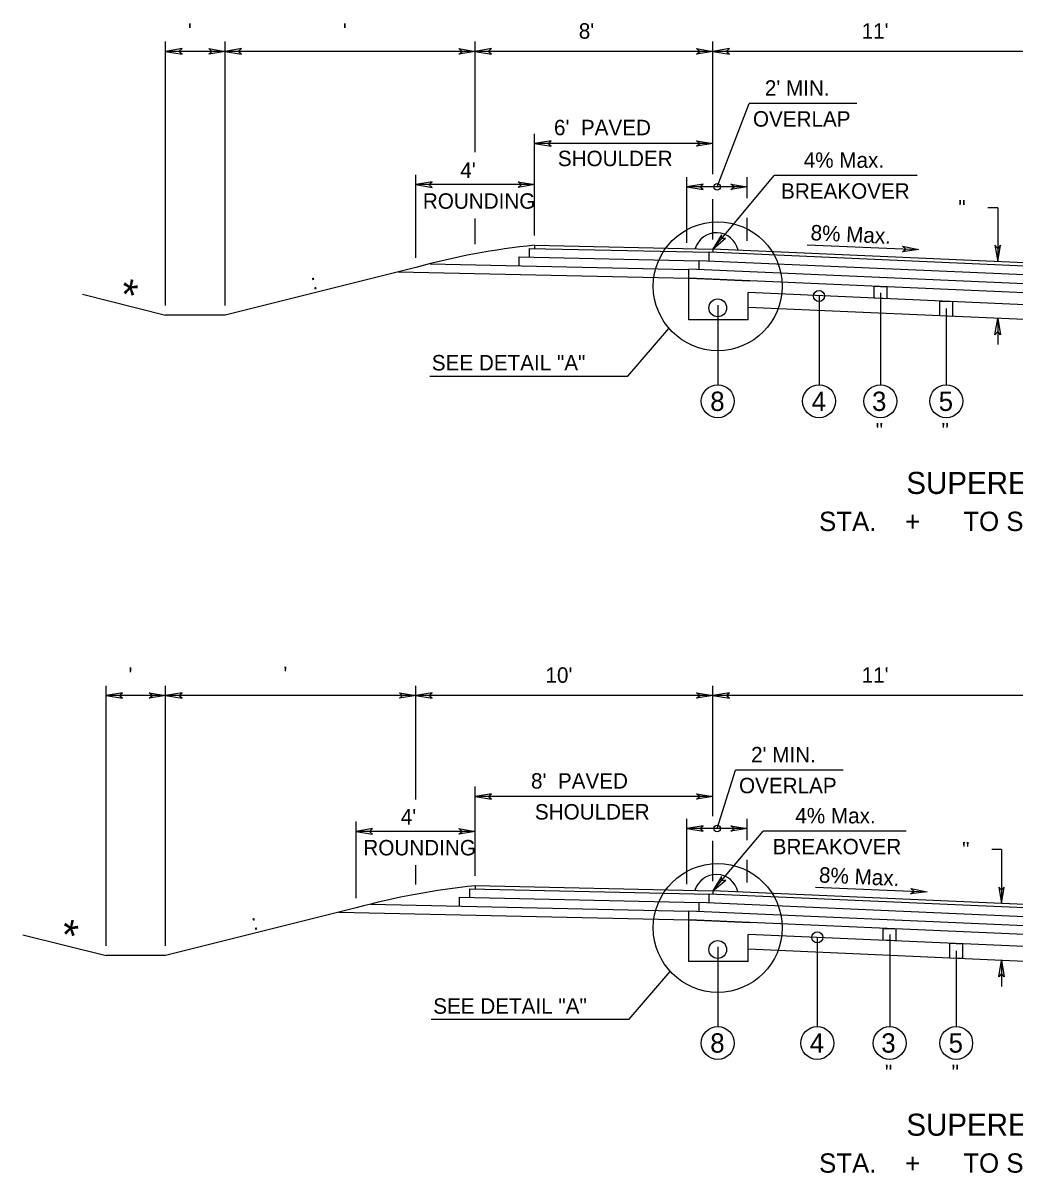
# Model space of a CAD drawing. Extents: x -592 to 1199, y -590 to 416.
# Drawn here: x 724.3 to 814.1, y 44 to 148.2 of the extents above; entities that cross this region are included whole.
import ezdxf

# ---------------------------------------------------------------- set-up
doc = ezdxf.new("R2010")
doc.units = 0
doc.layers.add('1', color=7, linetype='Continuous')
doc.layers.add('Des_ Drain_ Ftrs', color=7, linetype='Continuous')

msp = doc.modelspace()

# ---------------------------------------------------------------- linework, layer by layer
at = {"layer": '1'}
for p, q in [((737.21, 122.56), (737.21, 146.46)), ((742.6, 122.56), (742.6, 146.46)), ((765.26, 136.44), (765.26, 146.46)), ((786.81, 134.44), (786.81, 146.46)), ((742.6, 145.58), (737.21, 145.58)), ((765.26, 145.58), (742.6, 145.58)), ((786.81, 145.58), (765.26, 145.58)), ((816.45, 145.58), (786.81, 145.58)), ((787.18, 133.31), (790.09, 140.86)), ((799.85, 140.86), (790.09, 140.86)), ((770.65, 128.89), (770.65, 138.12)), ((786.81, 137.24), (770.65, 137.24)), ((759.87, 126.88), (759.87, 134.39)), ((770.65, 133.51), (759.87, 133.51)), ((784.44, 128.23), (784.44, 134.19)), ((786.81, 127.66), (792.34, 134.33)), ((789.92, 132.29), (789.92, 134.19)), ((805.31, 134.33), (792.34, 134.33)), ((789.92, 133.31), (784.44, 133.31)), ((786.81, 128.54), (786.81, 132.18)), ((812.61, 131.41), (811.73, 131.41)), ((812.61, 131.41), (812.61, 126.53)), ((765.26, 128.12), (765.26, 130.44)), ((789.92, 128.41), (789.92, 130.51)), ((770.18, 127.72), (786.47, 127.38)), ((770.18, 126.94), (770.18, 127.72)), ((770.65, 128.01), (786.81, 127.66)), ((770.65, 128.01), (770.65, 127.71)), ((816.45, 126.07), (786.47, 127.38)), ((786.47, 126.57), (786.47, 127.38)), ((816.45, 126.37), (786.81, 127.66)), ((786.81, 127.66), (786.81, 127.36)), ((795.35, 128.06), (805.46, 127.62)), ((761.17, 126.34), (784.58, 125.83)), ((769.25, 126.96), (785.52, 126.6)), ((769.25, 126.17), (769.25, 126.96)), ((816.45, 125.26), (785.55, 126.61)), ((785.55, 125.8), (785.55, 126.61)), ((759.87, 126), (742.6, 121.68)), ((758.28, 125.6), (784.62, 125.03)), ((816.45, 124.45), (784.62, 125.84)), ((784.62, 125.03), (784.62, 125.84)), ((784.62, 121.27), (784.62, 125.03)), ((816.45, 123.64), (784.62, 125.03)), ((784.62, 125.03), (786.81, 124.93)), ((786.81, 124.93), (790.11, 124.79)), ((729.67, 123.57), (737.21, 121.68)), ((816.45, 122.56), (790.01, 123.72)), ((790.01, 121.27), (790.01, 123.72)), ((796.42, 123.42), (796.42, 115.36)), ((801.98, 123.71), (801.98, 115.36)), ((787.24, 122.58), (787.24, 122.58)), ((787.24, 122.58), (787.24, 115.36)), ((816.45, 121.21), (790.01, 122.37)), ((807.95, 122.28), (807.95, 115.36)), ((742.6, 121.68), (737.21, 121.68)), ((790.01, 121.27), (784.62, 121.27)), ((812.61, 121.38), (812.61, 119.01)), ((779.08, 116.16), (782.82, 120.48)), ((761.15, 116.16), (779.08, 116.16)), ((731.82, 64.54), (731.82, 88.09)), ((737.21, 64.54), (737.21, 88.09)), ((759.87, 77.81), (759.87, 88.09)), ((786.81, 76.29), (786.81, 88.09)), ((737.21, 87.21), (731.82, 87.21)), ((759.87, 87.21), (737.21, 87.21)), ((786.81, 87.21), (759.87, 87.21)), ((816.45, 87.21), (786.81, 87.21)), ((787.18, 75.17), (788.84, 80.46)), ((798.6, 80.46), (788.84, 80.46)), ((765.26, 70.87), (765.26, 78.96)), ((786.81, 78.08), (765.26, 78.08)), ((754.49, 68.86), (754.49, 75.79)), ((784.44, 70.11), (784.44, 76.05)), ((789.92, 75.17), (784.44, 75.17)), ((789.92, 74.1), (789.92, 76.05)), ((765.26, 74.91), (754.49, 74.91)), ((786.81, 69.52), (791.37, 74.93)), ((786.81, 70.4), (786.81, 74.04)), ((804.3, 74.93), (791.37, 74.93)), ((812.96, 73.25), (812.08, 73.25)), ((812.96, 73.25), (812.96, 68.37)), ((789.92, 70.26), (789.92, 72.32)), ((759.87, 70.09), (759.87, 71.85)), ((765.26, 69.99), (786.81, 69.52)), ((765.26, 69.99), (765.26, 69.69)), ((796.1, 69.86), (806.22, 69.42)), ((763.84, 68.94), (785.55, 68.46)), ((763.84, 68.15), (763.84, 68.94)), ((764.77, 69.7), (786.47, 69.23)), ((764.77, 68.92), (764.77, 69.7)), ((816.45, 67.92), (786.47, 69.23)), ((786.47, 68.42), (786.47, 69.23)), ((816.45, 68.22), (786.81, 69.52)), ((786.81, 69.52), (786.81, 69.22)), ((754.49, 67.98), (737.21, 63.66)), ((755.81, 68.32), (784.62, 67.69)), ((816.45, 67.11), (785.55, 68.46)), ((785.55, 67.65), (785.55, 68.46)), ((752.89, 67.58), (784.62, 66.88)), ((816.45, 66.3), (784.62, 67.69)), ((784.62, 66.88), (784.62, 67.69)), ((784.62, 63.13), (784.62, 66.88)), ((816.45, 65.5), (784.62, 66.88)), ((784.62, 66.88), (786.81, 66.79)), ((786.81, 66.79), (790.11, 66.65)), ((724.28, 65.54), (731.82, 63.66)), ((816.45, 64.42), (790.01, 65.57)), ((790.01, 63.13), (790.01, 65.57)), ((796.26, 65.3), (796.26, 57.22)), ((802.82, 65.55), (802.82, 57.22)), ((737.21, 63.66), (731.82, 63.66)), ((787.24, 64.44), (787.24, 64.44)), ((787.24, 64.44), (787.24, 57.22)), ((816.45, 63.07), (790.01, 64.22)), ((808.85, 64.08), (808.85, 57.22)), ((790.01, 63.13), (784.62, 63.13)), ((812.96, 63.22), (812.96, 60.85)), ((779.2, 57.88), (782.94, 62.2)), ((761.27, 57.88), (779.2, 57.88))]:
    msp.add_line(p, q, dxfattribs=at)
for points in [[(801.41, 124.3), (802.55, 124.25), (802.55, 123.17), (801.41, 123.22)], [(807.37, 122.96), (808.52, 122.91), (808.52, 121.56), (807.37, 121.61)], [(802.24, 66.12), (803.39, 66.07), (803.39, 64.99), (802.24, 65.04)], [(808.28, 64.77), (809.43, 64.72), (809.43, 63.38), (808.28, 63.43)]]:
    msp.add_lwpolyline(points, close=True, dxfattribs=at)
for centre, radius in [((787.18, 133.31), 0.3), ((787.24, 124.3), 5.84), ((787.24, 122.34), 0.808), ((796.42, 123.42), 0.5), ((787.24, 113.88), 1.49), ((796.42, 113.88), 1.49), ((801.98, 113.88), 1.49), ((807.95, 113.88), 1.49), ((787.18, 75.17), 0.3), ((787.24, 66.16), 5.84), ((796.26, 65.3), 0.5), ((787.24, 64.2), 0.808), ((787.24, 55.73), 1.49), ((796.26, 55.73), 1.49), ((802.82, 55.73), 1.49), ((808.85, 55.73), 1.49)]:
    msp.add_circle(centre, radius, dxfattribs=at)
for centre, radius, start, end in [((787.12, 127.15), 2, 12.002, 163.9183), ((777.54, 61.18), 67.19, 95.8897, 105.2483), ((787.1, 69), 2, 12.0711, 163.96), ((772.16, 3.15), 67.19, 95.8911, 105.2497)]:
    msp.add_arc(centre, radius, start, end, dxfattribs=at)
at = {"layer": 'Des_ Drain_ Ftrs'}
for points in [[(737.21, 145.58), (738.7, 145.33), (738.4, 145.58), (738.7, 145.83)], [(742.6, 145.58), (741.11, 145.33), (741.4, 145.58), (741.11, 145.83)], [(742.6, 145.58), (744.08, 145.33), (743.79, 145.58), (744.08, 145.83)], [(765.26, 145.58), (763.77, 145.33), (764.07, 145.58), (763.77, 145.83)], [(765.26, 145.58), (766.75, 145.33), (766.45, 145.58), (766.75, 145.83)], [(786.81, 145.58), (785.33, 145.33), (785.62, 145.58), (785.33, 145.83)], [(786.81, 145.58), (788.3, 145.33), (788.01, 145.58), (788.3, 145.83)], [(770.65, 137.24), (772.14, 136.99), (771.84, 137.24), (772.14, 137.48)], [(786.81, 137.24), (785.33, 136.99), (785.62, 137.24), (785.33, 137.48)], [(759.87, 133.51), (761.36, 133.26), (761.07, 133.51), (761.36, 133.75)], [(770.65, 133.51), (769.16, 133.26), (769.46, 133.51), (769.16, 133.75)], [(784.44, 133.31), (785.93, 133.06), (785.63, 133.31), (785.93, 133.56)], [(789.92, 133.31), (788.44, 133.06), (788.73, 133.31), (788.44, 133.56)], [(786.81, 127.66), (787.95, 128.65), (787.57, 128.58), (787.57, 128.96)], [(805.46, 127.62), (803.97, 127.43), (804.27, 127.67), (803.99, 127.93)], [(812.61, 126.53), (812.86, 128.02), (812.61, 127.73), (812.36, 128.02)], [(812.61, 121.38), (812.86, 119.89), (812.61, 120.19), (812.36, 119.89)], [(731.82, 87.21), (733.31, 86.97), (733.01, 87.21), (733.31, 87.46)], [(737.21, 87.21), (735.72, 86.97), (736.01, 87.21), (735.72, 87.46)], [(737.21, 87.21), (738.7, 86.97), (738.4, 87.21), (738.7, 87.46)], [(759.87, 87.21), (758.39, 86.97), (758.68, 87.21), (758.39, 87.46)], [(759.87, 87.21), (761.36, 86.97), (761.07, 87.21), (761.36, 87.46)], [(786.81, 87.21), (785.33, 86.97), (785.62, 87.21), (785.33, 87.46)], [(786.81, 87.21), (788.3, 86.97), (788.01, 87.21), (788.3, 87.46)], [(765.26, 78.08), (766.75, 77.83), (766.45, 78.08), (766.75, 78.32)], [(786.81, 78.08), (785.33, 77.83), (785.62, 78.08), (785.33, 78.32)], [(754.49, 74.91), (755.97, 74.66), (755.68, 74.91), (755.97, 75.16)], [(765.26, 74.91), (763.77, 74.66), (764.07, 74.91), (763.77, 75.16)], [(784.44, 75.17), (785.93, 74.92), (785.63, 75.17), (785.93, 75.41)], [(789.92, 75.17), (788.44, 74.92), (788.73, 75.17), (788.44, 75.41)], [(786.81, 69.52), (787.96, 70.49), (787.58, 70.43), (787.58, 70.81)], [(812.96, 68.37), (813.21, 69.86), (812.96, 69.57), (812.71, 69.86)], [(806.22, 69.42), (804.72, 69.24), (805.03, 69.47), (804.74, 69.73)], [(812.96, 63.22), (813.21, 61.73), (812.96, 62.03), (812.71, 61.73)]]:
    msp.add_lwpolyline(points, close=True, dxfattribs=at)

# ---------------------------------------------------------------- texts
at = {"layer": '1'}
for s, height, p in [(" '", 1.4, (738.71, 146.73)), ("  '", 1.4, (752.23, 146.73)), ("8'", 1.4, (774.65, 146.73)), ("11'", 1.4, (800.28, 146.73)), ("2' MIN.", 1.4, (791.51, 141.56)), ('OVERLAP', 1.4, (790.43, 138.76)), ("6'  PAVED", 1.4, (772.4, 137.98)), ('SHOULDER', 1.4, (772.75, 135.18)), ("4'", 1.4, (763.91, 134.12)), ('4% Max.', 1.4, (795.03, 135.03)), ('BREAKOVER', 1.4, (792.98, 132.23)), ('ROUNDING', 1.4, (760.52, 131.32)), ('SEE DETAIL "A"', 1.4, (761.33, 116.67)), ('8', 1.75, (786.56, 113)), ('4', 1.75, (795.75, 113)), ('3', 1.75, (801.22, 113)), ('5', 1.75, (807.26, 113)), (' "', 1.4, (801.04, 110.52)), (' "', 1.4, (807, 110.52)), ('SUPERELEVATED', 2, (804.33, 105.48)), ('STA.    +      TO STA.    +     ', 1.75, (796.42, 102.12)), (" '", 1.4, (733.32, 88.37)), ("  '", 1.4, (746.84, 88.44)), ("10'", 1.4, (771.63, 88.37)), ("11'", 1.4, (800.28, 88.37)), ("2' MIN.", 1.4, (790.26, 81.16)), ("8'  PAVED", 1.4, (770.32, 78.78)), ('OVERLAP', 1.4, (789.17, 78.36)), ('SHOULDER', 1.4, (770.67, 75.98)), ("4'", 1.4, (758.52, 75.53)), ('4% Max.', 1.4, (794.27, 75.63)), ('ROUNDING', 1.4, (755.13, 72.73)), ('BREAKOVER', 1.4, (792.22, 72.83)), ('SEE DETAIL "A"', 1.4, (761.46, 58.38)), ('8', 1.75, (786.56, 54.86)), ('4', 1.75, (795.58, 54.86)), ('3', 1.75, (802.06, 54.86)), ('5', 1.75, (808.16, 54.86)), (' "', 1.4, (801.87, 52.37)), (' "', 1.4, (807.91, 52.37)), ('SUPERELEVATED', 2, (804.33, 47.33)), ('STA.    +      TO STA.    +     ', 1.75, (796.42, 43.98))]:
    msp.add_text(s, height=height, dxfattribs=at).set_placement(p)
for s, height, rotation, p in [('  "', 1.4, 0.1438, (808, 130.71)), ('8% Max.', 1.4, 357.3763, (795.63, 128.47)), (' : ', 1.4, 14.2282, (750.05, 123.83)), ('*', 2.8, 347.1521, (732.84, 122.33)), ('  "', 1.4, 0.1438, (808.35, 72.55)), ('8% Max.', 1.4, 357.3756, (796.39, 70.28)), ('*', 2.8, 347.1521, (727.45, 64.3)), (' : ', 1.4, 14.2282, (744.67, 65.8))]:
    msp.add_text(s, height=height, rotation=rotation, dxfattribs=at).set_placement(p)

doc.saveas('drawing.dxf')
